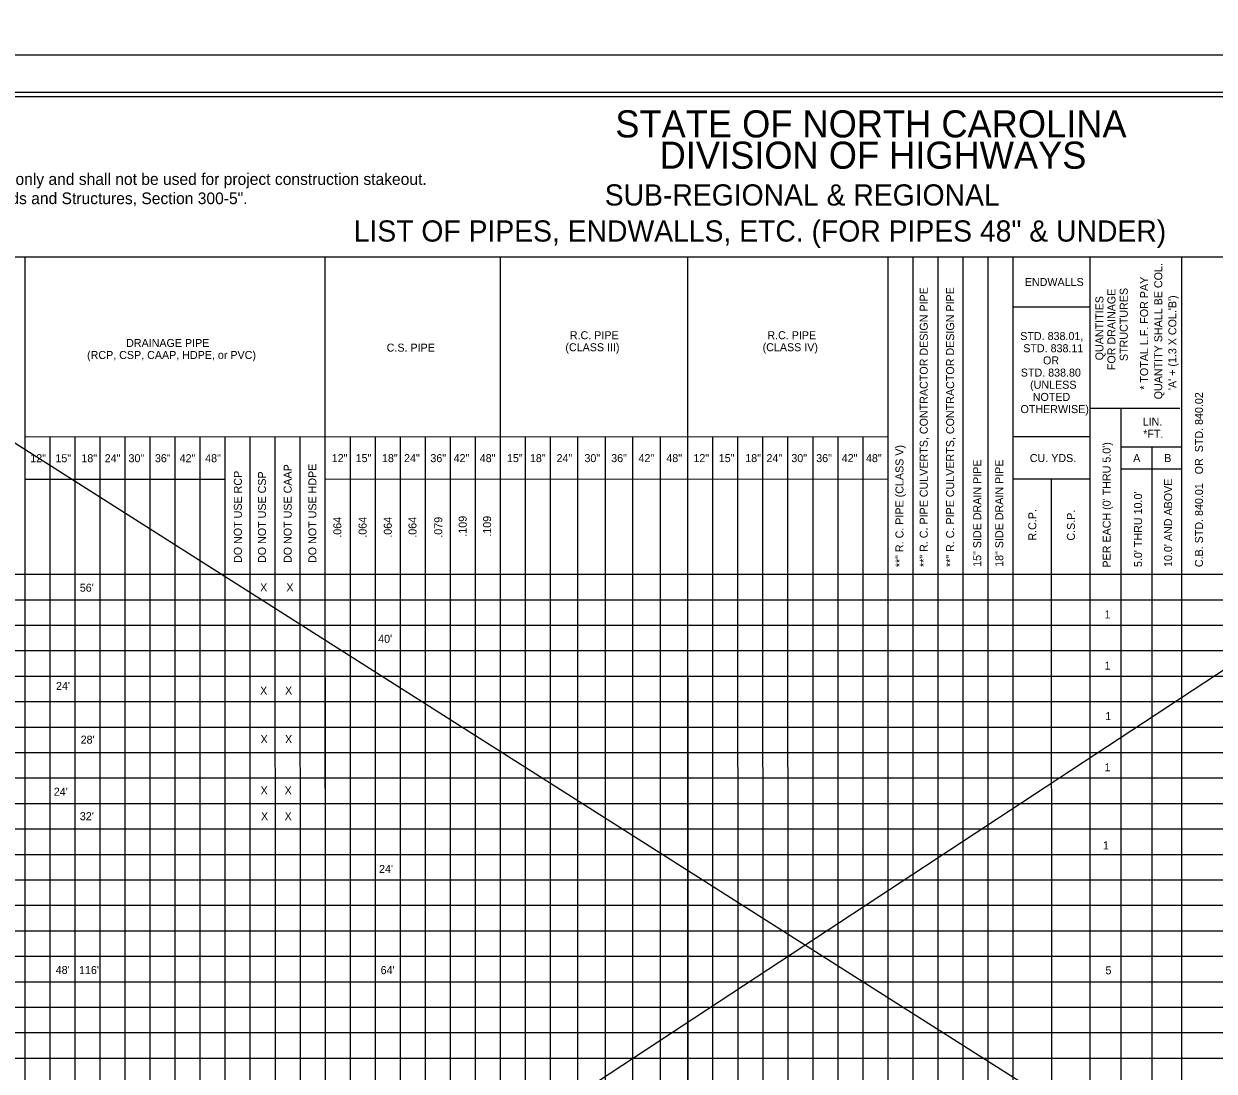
# Model space of a CAD drawing. Extents: x 573359 to 575895, y -54193 to -50493.
# Drawn here: x 574005 to 574719, y -52448 to -51820 of the extents above; entities that cross this region are included whole.
import ezdxf

# ---------------------------------------------------------------- set-up
doc = ezdxf.new("R2010")
doc.units = 0
for name, color, linetype in [('Prop Dimension Text', 7, 'Continuous'), ('Sheet Cutting Line CELL', 7, 'Continuous'), ('Sheet Pipe Summary CELL', 7, 'Continuous'), ('Sheet Pipe Summary Grid CELL', 7, 'Continuous'), ('Sheet Plot Border Inside CELL', 7, 'Continuous'), ('Sheet Plot Border Outside CELL', 7, 'Continuous')]:
    doc.layers.add(name, color=color, linetype=linetype)

msp = doc.modelspace()

# ---------------------------------------------------------------- linework, layer by layer
at = {"layer": 'Prop Dimension Text'}
for p, q in [((575553.79, -51662.96), (573359.5, -53105.6)), ((573527.78, -51771.9), (575540.59, -53049.47))]:
    msp.add_line(p, q, dxfattribs=at)
at = {"layer": 'Sheet Cutting Line CELL'}
msp.add_line((575302.66, -51839.08), (573618.66, -51839.08), dxfattribs=at)
at = {"layer": 'Sheet Pipe Summary CELL'}
msp.add_lwpolyline([(575285.66, -51864.08), (573785.66, -51864.08), (573785.66, -52914.08), (575285.66, -52914.08)], close=True, dxfattribs=at)
at = {"layer": 'Sheet Pipe Summary Grid CELL'}
for p, q in [((575285.66, -51960.18), (573785.66, -51960.28)), ((574006.38, -52914.07), (574006.33, -51960.27)), ((574186.38, -52914.06), (574186.33, -51960.25)), ((574291.38, -52914.06), (574291.33, -51960.25)), ((574403.93, -52913.96), (574403.83, -51960.16)), ((574523.93, -52913.97), (574523.83, -51960.17)), ((574538.93, -52913.97), (574538.83, -51960.17)), ((574553.93, -52913.97), (574553.83, -51960.17)), ((574568.93, -52913.97), (574568.83, -51960.17)), ((574583.93, -52913.97), (574583.83, -51960.17)), ((574598.93, -52913.97), (574598.83, -51960.17)), ((574598.88, -52914.02), (574598.83, -51960.17)), ((574598.93, -52913.97), (574598.83, -51960.17)), ((574645.18, -52914.02), (574645.08, -51960.22)), ((574700.18, -52914.02), (574700.08, -51960.22)), ((574700.18, -52914.02), (574700.08, -51960.22)), ((574645.08, -51990.17), (574598.83, -51990.17)), ((574698.83, -52050.92), (574645.09, -52050.92)), ((574663.78, -52914.02), (574663.68, -52050.92)), ((574523.84, -52068.05), (574006.34, -52068.12)), ((574021.38, -52914.07), (574021.34, -52068.12)), ((574036.38, -52914.07), (574036.34, -52068.12)), ((574051.38, -52914.07), (574051.34, -52068.12)), ((574066.38, -52914.07), (574066.34, -52068.11)), ((574081.38, -52914.07), (574081.34, -52068.11)), ((574096.38, -52914.07), (574096.34, -52068.11)), ((574111.38, -52914.07), (574111.34, -52068.11)), ((574126.38, -52914.07), (574126.34, -52068.11)), ((574141.38, -52914.06), (574141.34, -52068.11)), ((574156.38, -52914.06), (574156.34, -52068.11)), ((574171.38, -52914.06), (574171.34, -52068.11)), ((574201.38, -52914.06), (574201.34, -52068.11)), ((574216.38, -52914.06), (574216.34, -52068.09)), ((574231.38, -52914.06), (574231.34, -52068.11)), ((574246.38, -52914.06), (574246.34, -52068.08)), ((574261.38, -52914.06), (574261.34, -52068.1)), ((574276.38, -52914.06), (574276.34, -52068.08)), ((574291.38, -52914.06), (574291.34, -52068.1)), ((574306.38, -52914.06), (574306.34, -52068.08)), ((574321.38, -52914.05), (574321.34, -52068.08)), ((574337.88, -52914.05), (574337.84, -52068.07)), ((574354.38, -52914.05), (574354.34, -52068.07)), ((574370.88, -52914.05), (574370.84, -52068.07)), ((574387.38, -52914.05), (574387.34, -52068.07)), ((574403.88, -52914.05), (574403.84, -52068.07)), ((574418.88, -52914.05), (574418.84, -52068.07)), ((574433.88, -52914.05), (574433.84, -52068.07)), ((574448.88, -52914.05), (574448.84, -52068.07)), ((574463.88, -52914.05), (574463.84, -52068.06)), ((574478.88, -52914.05), (574478.84, -52068.06)), ((574493.88, -52914.05), (574493.84, -52068.06)), ((574508.88, -52914.05), (574508.84, -52068.06)), ((574523.88, -52914.04), (574523.84, -52068.06)), ((574645.08, -52068.02), (574598.83, -52068.02)), ((574700.08, -52074.12), (574663.68, -52074.12)), ((574682.33, -52914.02), (574682.23, -52074.12)), ((574700.08, -52087.32), (574663.68, -52087.32)), ((574126.34, -52093.49), (574006.34, -52093.5)), ((574523.84, -52093.45), (574186.34, -52093.49)), ((574186.38, -52914.06), (574186.34, -52093.49)), ((574645.08, -52093.42), (574598.83, -52093.42)), ((574622.03, -52914.02), (574621.98, -52093.42)), ((575285.66, -52150.58), (573785.66, -52150.58)), ((575285.66, -52165.88), (573785.66, -52165.88)), ((575285.66, -52181.13), (573785.66, -52181.13)), ((575285.66, -52196.38), (573785.66, -52196.38)), ((575285.66, -52211.68), (573785.66, -52211.68)), ((575285.66, -52226.93), (573785.66, -52226.93)), ((575285.66, -52242.23), (573785.66, -52242.23)), ((575285.66, -52257.48), (573785.66, -52257.48)), ((575285.66, -52272.73), (573785.66, -52272.73)), ((575285.66, -52288.03), (573785.66, -52288.03)), ((575285.66, -52303.28), (573785.66, -52303.28)), ((575285.66, -52318.58), (573785.66, -52318.58)), ((575285.66, -52333.83), (573785.66, -52333.83)), ((575285.66, -52349.08), (573785.66, -52349.08)), ((575285.66, -52364.38), (573785.66, -52364.38)), ((575285.66, -52379.63), (573785.66, -52379.63)), ((575285.66, -52394.93), (573785.66, -52394.93)), ((575285.66, -52410.18), (573785.66, -52410.18)), ((575285.66, -52425.43), (573785.66, -52425.43)), ((575285.66, -52440.73), (573785.66, -52440.73))]:
    msp.add_line(p, q, dxfattribs=at)
at = {"layer": 'Sheet Plot Border Inside CELL'}
msp.add_lwpolyline([(573631.66, -52916.63), (575298.16, -52916.63), (575298.16, -51861.53), (573631.66, -51861.53)], close=True, dxfattribs=at)
at = {"layer": 'Sheet Plot Border Outside CELL'}
msp.add_lwpolyline([(573618.66, -52939.08), (575302.66, -52939.08), (575302.66, -51839.08), (573618.66, -51839.08)], close=True, dxfattribs=at)

# ---------------------------------------------------------------- texts
at = {"layer": 'Prop Dimension Text'}
for s, p in [("56'", (574039.08, -52160.86)), ('X', (574147.23, -52160.69)), ('X', (574162.98, -52160.69)), ('1', (574653.67, -52176.91)), ("40'", (574218.03, -52191.5)), ('1', (574653.67, -52207.59)), ("24'", (574024.79, -52219.78)), ('X', (574147.23, -52222.52)), ('X', (574162.2, -52222.52)), ('1', (574654.16, -52237.83)), ("28'", (574039.58, -52251.97)), ('X', (574147.5, -52251.67)), ('X', (574162.2, -52251.67)), ('1', (574653.67, -52268.55)), ("24'", (574023.49, -52283.18)), ('X', (574147.5, -52282.38)), ('X', (574161.93, -52282.38)), ("32'", (574039.1, -52297.87)), ('X', (574147.76, -52297.87)), ('X', (574161.93, -52297.87)), ('1', (574652.7, -52315.36)), ("24'", (574218.58, -52329.5)), ("48'", (574024.63, -52390.05)), ("116'", (574038.62, -52390.12)), ("64'", (574219.51, -52390.17)), ('5', (574654.26, -52390.27))]:
    msp.add_text(s, height=4.8, dxfattribs=at).set_placement(p)
at = {"layer": 'Sheet Pipe Summary CELL'}
for s, height, p in [('STATE OF NORTH CAROLINA', 16.2501, (574360.26, -51888.48)), ('DIVISION OF HIGHWAYS', 16.2501, (574386.86, -51907.23)), ('NOTE: Invert Elevations are for Bid Purposes only and shall not be used for project construction stakeout.', 7, (573809.57, -51916.95)), ('SUB-REGIONAL & REGIONAL', 12.6999, (574353.92, -51929.31)), ('See "Standard Specifications For Roads and Structures, Section 300-5".', 7, (573840.1, -51928.48)), ('LIST OF PIPES, ENDWALLS, ETC. (FOR PIPES 48" & UNDER)', 12.6999, (574203.36, -51950.93)), ('ENDWALLS', 4.8, (574605.88, -51977.57)), ('R.C. PIPE', 4.8, (574333.01, -52009.48)), ('R.C. PIPE', 4.8, (574451.47, -52009.48)), ('STD. 838.01,', 4.8, (574603.15, -52009.97)), ('DRAINAGE PIPE', 4.8, (574066.85, -52014.12)), ('C.S. PIPE', 4.8, (574223.14, -52016.92)), ('(CLASS III)', 4.8, (574330.32, -52016.68)), ('(CLASS IV)', 4.8, (574448.63, -52016.68)), ('STD. 838.11', 4.8, (574604.95, -52017.27)), ('(RCP, CSP, CAAP, HDPE, or PVC)', 4.8, (574043.44, -52021.32)), ('OR', 4.8, (574616.8, -52024.57)), ('STD. 838.80', 4.8, (574603.48, -52031.87)), ('(UNLESS', 4.8, (574609.05, -52039.17)), ('NOTED', 4.8, (574610.65, -52046.47)), ('OTHERWISE)', 4.8, (574603.3, -52053.77)), ('LIN.', 4.8, (574676.58, -52061.27)), ('*FT.', 4.8, (574676.88, -52068.57)), ('12"', 4.8, (574009.38, -52083.22)), ('15"', 4.8, (574024.45, -52083.22)), ('18"', 4.8, (574040.03, -52083.22)), ('24"', 4.8, (574054.01, -52083.22)), ('30"', 4.8, (574068.31, -52083.22)), ('36"', 4.8, (574084.14, -52083.22)), ('42"', 4.8, (574098.95, -52083.22)), ('48"', 4.8, (574114.27, -52083.22)), ('12"', 4.8, (574190.17, -52083.17)), ('15"', 4.8, (574204.53, -52083.17)), ('18"', 4.8, (574220.32, -52083.17)), ('24"', 4.8, (574233.56, -52083.17)), ('36"', 4.8, (574249.35, -52083.17)), ('42"', 4.8, (574263.29, -52083.17)), ('48"', 4.8, (574278.96, -52083.17)), ('15"', 4.8, (574295.28, -52083.16)), ('18"', 4.8, (574309.06, -52083.16)), ('24"', 4.8, (574325.04, -52083.16)), ('30"', 4.8, (574341.76, -52083.16)), ('36"', 4.8, (574357.8, -52083.16)), ('42"', 4.8, (574374.18, -52083.16)), ('48"', 4.8, (574390.9, -52083.16)), ('12"', 4.8, (574407.11, -52083.16)), ('15"', 4.8, (574422.32, -52083.16)), ('18"', 4.8, (574438.22, -52083.16)), ('24"', 4.8, (574450.94, -52083.16)), ('30"', 4.8, (574465.85, -52083.16)), ('36"', 4.8, (574480.77, -52083.16)), ('42"', 4.8, (574496.05, -52083.16)), ('48"', 4.8, (574510.61, -52083.16)), ('CU. YDS.', 4.8, (574608.88, -52083.12)), ('A', 4.8, (574670.88, -52083.12)), ('B', 4.8, (574689.48, -52083.12))]:
    msp.add_text(s, height=height, dxfattribs=at).set_placement(p)
for s, height, rotation, p in [('QUANTITY SHALL BE COL.', 4.8, 90, (574688.33, -52045.52)), ('* TOTAL L.F. FOR PAY', 4.8, 90, (574679.83, -52039.77)), ('**" R. C. PIPE CULVERTS, CONTRACTOR DESIGN PIPE', 4.8, 90, (574547.66, -52146.05)), ('**" R. C. PIPE CULVERTS, CONTRACTOR DESIGN PIPE', 4.8, 90, (574563.49, -52146.05)), ('QUANTITIES', 4.8, 90, (574653.03, -52022.12)), ('FOR DRAINAGE', 4.8, 90, (574660.23, -52028.02)), ('STRUCTURES', 4.8, 90, (574667.63, -52022.57)), ("'A' + (1.3 X COL.'B')", 4.8, 90, (574696.78, -52039.97)), ('C.B. STD. 840.01   OR  STD. 840.02', 4.8, 90, (574712.73, -52146.12)), ('**" R. C. PIPE (CLASS V)', 4.8, 90, (574533.1, -52146.15)), ("PER EACH (0' THRU 5.0')", 4.7986, 90.03687, (574657.38, -52146.37)), ('15" SIDE DRAIN PIPE', 4.8, 90, (574579.71, -52145.95)), ('18" SIDE DRAIN PIPE', 4.8, 90, (574592.95, -52145.95)), ('DO NOT USE RCP', 4.8, 90, (574136.28, -52143.63)), ('DO NOT USE CSP', 4.8, 90, (574150.74, -52143.63)), ('DO NOT USE CAAP', 4.8, 90, (574166.16, -52143.63)), ('DO NOT USE HDPE', 4.8, 90, (574180.97, -52143.63)), ("10.0' AND ABOVE", 4.8, 90, (574694.23, -52146.02)), ("5.0' THRU 10.0'", 4.8, 90, (574676.18, -52146.07)), ('R.C.P.', 4.8, 90, (574612.78, -52130.22)), ('C.S.P.', 4.8, 90, (574635.93, -52130.22)), ('.064', 4.8, 90, (574195.95, -52128.49)), ('.064', 4.8, 90, (574211.08, -52128.49)), ('.064', 4.8, 90, (574226.21, -52128.49)), ('.064', 4.8, 90, (574241.02, -52128.49)), ('.079', 4.8, 90, (574256.48, -52128.47)), ('.109', 4.8, 90, (574271.11, -52127.87)), ('.109', 4.8, 90, (574285.76, -52127.87))]:
    msp.add_text(s, height=height, rotation=rotation, dxfattribs=at).set_placement(p)

doc.saveas('drawing.dxf')
